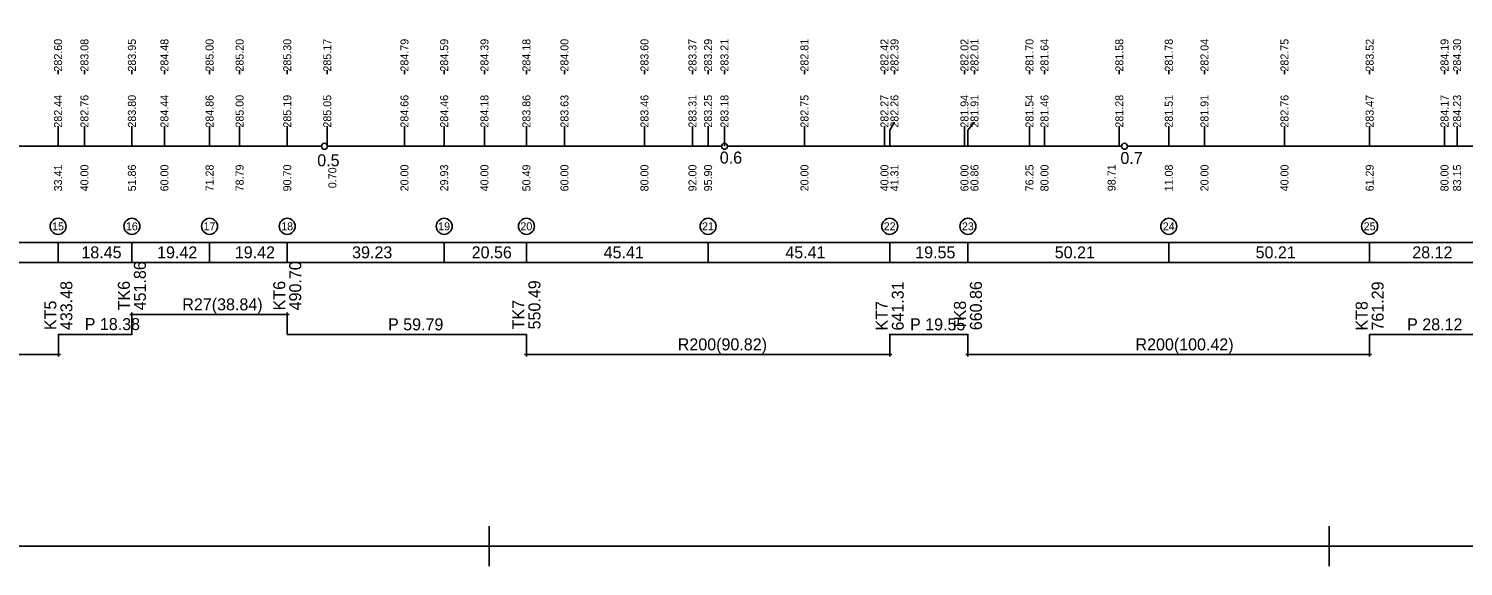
# Model space of a CAD drawing. Extents: x -24 to 1036, y -50 to 554.
# Drawn here: x 496.1 to 854.7, y -50 to 84.4 of the extents above; entities that cross this region are included whole.
import ezdxf

# ---------------------------------------------------------------- set-up
doc = ezdxf.new("R2010")
doc.units = 0
for name, color, linetype in [('SESTAVY_REZU_PO', 7, 'Continuous'), ('SMEROVE_POMERY', 7, 'Continuous'), ('SMEROVE_POMERY_KOD', 7, 'Continuous'), ('SVK', 7, 'Continuous'), ('SVK_STAT', 7, 'Continuous'), ('TABULKY', 7, 'Continuous')]:
    doc.layers.add(name, color=color, linetype=linetype)

msp = doc.modelspace()

# ---------------------------------------------------------------- linework, layer by layer
for p, q in [((611.15, -39.96), (611.15, -49.96)), ((611.15, -39.96), (611.15, -49.96)), ((611.15, -39.96), (611.15, -49.96)), ((611.15, -39.96), (611.15, -49.96)), ((611.15, -39.96), (611.15, -49.96)), ((611.15, -39.96), (611.15, -49.96)), ((611.15, -39.96), (611.15, -49.96)), ((611.15, -39.96), (611.15, -49.96)), ((611.15, -39.96), (611.15, -49.96)), ((611.15, -39.96), (611.15, -49.96)), ((611.15, -39.96), (611.15, -49.96)), ((611.15, -39.96), (611.15, -49.96)), ((611.15, -39.96), (611.15, -49.96)), ((611.15, -39.96), (611.15, -49.96)), ((611.15, -39.96), (611.15, -49.96)), ((611.15, -39.96), (611.15, -49.96)), ((821.15, -39.96), (821.15, -49.96)), ((821.15, -39.96), (821.15, -49.96)), ((821.15, -39.96), (821.15, -49.96)), ((821.15, -39.96), (821.15, -49.96)), ((821.15, -39.96), (821.15, -49.96)), ((821.15, -39.96), (821.15, -49.96)), ((821.15, -39.96), (821.15, -49.96)), ((821.15, -39.96), (821.15, -49.96)), ((616.15, -44.96), (606.15, -44.96)), ((616.15, -44.96), (606.15, -44.96)), ((616.15, -44.96), (606.15, -44.96)), ((616.15, -44.96), (606.15, -44.96)), ((616.15, -44.96), (606.15, -44.96)), ((616.15, -44.96), (606.15, -44.96)), ((616.15, -44.96), (606.15, -44.96)), ((616.15, -44.96), (606.15, -44.96)), ((616.15, -44.96), (606.15, -44.96)), ((616.15, -44.96), (606.15, -44.96)), ((616.15, -44.96), (606.15, -44.96)), ((616.15, -44.96), (606.15, -44.96)), ((616.15, -44.96), (606.15, -44.96)), ((616.15, -44.96), (606.15, -44.96)), ((616.15, -44.96), (606.15, -44.96)), ((616.15, -44.96), (606.15, -44.96)), ((826.15, -44.96), (816.15, -44.96)), ((826.15, -44.96), (816.15, -44.96)), ((826.15, -44.96), (816.15, -44.96)), ((826.15, -44.96), (816.15, -44.96)), ((826.15, -44.96), (816.15, -44.96)), ((826.15, -44.96), (816.15, -44.96)), ((826.15, -44.96), (816.15, -44.96)), ((826.15, -44.96), (816.15, -44.96))]:
    msp.add_line(p, q)
msp.add_lwpolyline([(1031.15, 549.04), (-19.35, 549.04), (-19.35, -44.96), (1031.15, -44.96)], close=True)
msp.add_lwpolyline([(1031.15, 549.04), (-19.35, 549.04), (-19.35, -44.96), (1031.15, -44.96)], close=True)
at = {"layer": 'SESTAVY_REZU_PO'}
for points in [[(470.75, 55), (569.25, 55)], [(570.75, 55), (669.25, 55)], [(670.75, 55), (769.25, 55)], [(770.75, 55), (859.4, 55)], [(503.41, 26), (503.41, 31)], [(521.86, 26), (521.86, 31)], [(541.28, 26), (541.28, 31)], [(560.7, 26), (560.7, 31)], [(599.93, 26), (599.93, 31)], [(620.49, 26), (620.49, 31)], [(665.9, 26), (665.9, 31)], [(711.31, 26), (711.31, 31)], [(730.86, 26), (730.86, 31)], [(781.08, 26), (781.08, 31)], [(831.29, 26), (831.29, 31)]]:
    msp.add_lwpolyline(points, dxfattribs=at)
for centre in [(570, 55), (670, 55), (770, 55)]:
    msp.add_circle(centre, 0.75, dxfattribs=at)
at = {"layer": 'SMEROVE_POMERY'}
msp.add_lwpolyline([(445.06, 3), (503.48, 3), (503.48, 8), (521.86, 8), (521.86, 13), (560.7, 13), (560.7, 8), (620.49, 8), (620.49, 3), (711.31, 3), (711.31, 8), (730.86, 8), (730.86, 3), (831.29, 3), (831.29, 8), (859.4, 8)], dxfattribs=at)
at = {"layer": 'SMEROVE_POMERY_KOD'}
for points in [[(521.36, 13), (522.36, 13)], [(521.86, 12.5), (521.86, 13.5)], [(560.2, 13), (561.2, 13)], [(560.7, 12.5), (560.7, 13.5)], [(502.98, 3), (503.98, 3)], [(503.48, 2.5), (503.48, 3.5)], [(619.99, 3), (620.99, 3)], [(620.49, 2.5), (620.49, 3.5)], [(710.81, 3), (711.81, 3)], [(711.31, 2.5), (711.31, 3.5)], [(730.36, 3), (731.36, 3)], [(730.86, 2.5), (730.86, 3.5)], [(830.79, 3), (831.79, 3)], [(831.29, 2.5), (831.29, 3.5)]]:
    msp.add_lwpolyline(points, dxfattribs=at)
at = {"layer": 'SVK'}
for points in [[(510, 73), (510, 74)], [(530, 73), (530, 74)], [(590, 73), (590, 74)], [(610, 73), (610, 74)], [(630, 73), (630, 74)], [(650, 73), (650, 74)], [(670, 73), (670, 74)], [(690, 73), (690, 74)], [(710, 73), (710, 74)], [(730, 73), (730, 74)], [(750, 73), (750, 74)], [(790, 73), (790, 74)], [(810, 73), (810, 74)], [(850, 73), (850, 74)], [(853.15, 73), (853.15, 74)], [(510, 55), (510, 60)], [(530, 55), (530, 60)], [(590, 55), (590, 60)], [(610, 55), (610, 60)], [(630, 55), (630, 60)], [(650, 55), (650, 60)], [(670, 55), (670, 60)], [(690, 55), (690, 60)], [(710, 55), (710, 60)], [(730, 55), (730, 60)], [(750, 55), (750, 60)], [(790, 55), (790, 60)], [(810, 55), (810, 60)], [(850, 55), (850, 60)], [(853.15, 55), (853.15, 60)]]:
    msp.add_lwpolyline(points, dxfattribs=at)
at = {"layer": 'SVK_STAT'}
for points in [[(503.41, 73), (503.41, 74)], [(521.86, 73), (521.86, 74)], [(541.28, 73), (541.28, 74)], [(548.79, 73), (548.79, 74)], [(560.7, 73), (560.7, 74)], [(570.7, 73), (570.7, 74)], [(599.93, 73), (599.93, 74)], [(620.49, 73), (620.49, 74)], [(662, 73), (662, 74)], [(665.9, 73), (665.9, 74)], [(712.5, 73), (712.5, 74)], [(732.5, 73), (732.5, 74)], [(746.25, 73), (746.25, 74)], [(768.71, 73), (768.71, 74)], [(781.08, 73), (781.08, 74)], [(831.29, 73), (831.29, 74)], [(711.31, 55), (711.31, 59), (712.5, 61)], [(730.86, 55), (730.86, 59), (732.5, 61)], [(503.41, 55), (503.41, 60)], [(521.86, 55), (521.86, 60)], [(541.28, 55), (541.28, 60)], [(548.79, 55), (548.79, 60)], [(560.7, 55), (560.7, 60)], [(570.7, 55), (570.7, 60)], [(599.93, 55), (599.93, 60)], [(620.49, 55), (620.49, 60)], [(662, 55), (662, 60)], [(665.9, 55), (665.9, 60)], [(746.25, 55), (746.25, 60)], [(768.71, 55), (768.71, 60)], [(781.08, 55), (781.08, 60)], [(831.29, 55), (831.29, 60)]]:
    msp.add_lwpolyline(points, dxfattribs=at)
for centre in [(503.41, 35), (521.86, 35), (541.28, 35), (560.7, 35), (599.93, 35), (620.49, 35), (665.9, 35), (711.31, 35), (730.86, 35), (781.08, 35), (831.29, 35)]:
    msp.add_circle(centre, 2, dxfattribs=at)
at = {"layer": 'TABULKY'}
msp.add_lwpolyline([(70, 26), (859.4, 26), (859.4, 31), (70, 31), (70, 26)], dxfattribs=at)

# ---------------------------------------------------------------- texts
at = {"layer": 'SESTAVY_REZU_PO'}
for s, p in [('0.5', (568.2, 50)), ('0.6', (668.83, 50.68)), ('0.7', (768.98, 50.58)), ('18.45', (509.24, 27)), ('19.42', (528.17, 27)), ('19.42', (547.59, 27)), ('39.23', (576.92, 27)), ('20.56', (606.81, 27)), ('45.41', (639.8, 27)), ('45.41', (685.21, 27)), ('19.55', (717.69, 27)), ('50.21', (752.57, 27)), ('50.21', (802.78, 27)), ('28.12', (841.95, 27))]:
    msp.add_text(s, height=3, dxfattribs=at).set_placement(p)
at = {"layer": 'SMEROVE_POMERY'}
for s, p in [('R27(38.84)', (534.47, 14)), ('P 18.38', (510.07, 9.07)), ('P 59.79', (585.9, 9)), ('P 19.55', (716.39, 9)), ('P 28.12', (840.65, 9)), ('R200(90.82)', (658.33, 4)), ('R200(100.42)', (772.75, 4))]:
    msp.add_text(s, height=3, dxfattribs=at).set_placement(p)
at = {"layer": 'SMEROVE_POMERY_KOD'}
for s, p in [('451.86', (525.36, 14)), ('490.70', (564.2, 14)), ('433.48', (506.98, 9.07)), ('TK6', (521.36, 14)), ('KT6', (560.2, 14)), ('550.49', (623.99, 9.24)), ('641.31', (714.81, 8.96)), ('660.86', (734.36, 9.03)), ('761.29', (834.79, 8.95)), ('KT5', (502.98, 9.07)), ('TK7', (619.99, 9.24)), ('KT7', (710.81, 8.96)), ('TK8', (730.36, 9.03)), ('KT8', (830.79, 8.95))]:
    msp.add_text(s, height=3, rotation=90, dxfattribs=at).set_placement(p)
at = {"layer": 'SVK'}
for s, p in [(' 283.08', (511, 72.93)), (' 284.48', (531, 72.93)), (' 284.79', (591, 72.93)), (' 284.39', (611, 72.93)), (' 284.00', (631, 72.93)), (' 283.60', (651, 72.93)), (' 283.21', (671, 72.93)), (' 282.81', (691, 72.93)), (' 282.42', (711, 72.93)), (' 282.02', (731, 72.93)), (' 281.64', (751, 72.93)), (' 282.04', (791, 72.93)), (' 282.75', (811, 72.93)), (' 284.19', (851, 72.93)), (' 284.30', (854.15, 72.93)), (' 282.76', (511, 58.93)), (' 284.44', (531, 58.93)), (' 284.66', (591, 58.93)), (' 284.18', (611, 58.93)), (' 283.63', (631, 58.93)), (' 283.46', (651, 58.93)), (' 283.18', (671, 58.93)), (' 282.75', (691, 58.93)), (' 282.27', (711, 58.93)), (' 281.94', (731, 58.93)), (' 281.46', (751, 58.93)), (' 281.91', (791, 58.93)), (' 282.76', (811, 58.93)), (' 284.17', (851, 58.93)), (' 284.23', (854.15, 58.93)), (' 40.00', (511, 43)), (' 60.00', (531, 43)), (' 20.00', (591, 43)), (' 40.00', (611, 43)), (' 60.00', (631, 43)), (' 80.00', (651, 43)), (' 20.00', (691, 43)), (' 40.00', (711, 43)), (' 60.00', (731, 43)), (' 80.00', (751, 43)), (' 20.00', (791, 43)), (' 40.00', (811, 43)), (' 80.00', (851, 43)), (' 83.15', (854.15, 43))]:
    msp.add_text(s, height=2, rotation=90, dxfattribs=at).set_placement(p)
at = {"layer": 'SVK_STAT'}
for s, p in [(' 282.60', (504.41, 72.93)), (' 283.95', (522.86, 72.93)), (' 285.00', (542.28, 72.93)), (' 285.20', (549.79, 72.93)), (' 285.30', (561.7, 72.93)), (' 285.17', (571.7, 72.93)), (' 284.59', (600.93, 72.93)), (' 284.18', (621.49, 72.93)), (' 283.37', (663, 72.93)), (' 283.29', (666.9, 72.93)), (' 282.39', (713.5, 72.93)), (' 282.01', (733.5, 72.93)), (' 281.70', (747.25, 72.93)), (' 281.58', (769.71, 72.93)), (' 281.78', (782.08, 72.93)), (' 283.52', (832.29, 72.93)), (' 282.44', (504.41, 58.93)), (' 283.80', (522.86, 58.93)), (' 284.86', (542.28, 58.93)), (' 285.00', (549.79, 58.93)), (' 285.19', (561.7, 58.93)), (' 285.05', (571.7, 58.93)), (' 284.46', (600.93, 58.93)), (' 283.86', (621.49, 58.93)), (' 283.31', (663, 58.93)), (' 283.25', (666.9, 58.93)), (' 282.26', (713.5, 58.93)), (' 281.91', (733.5, 58.93)), (' 281.54', (747.25, 58.93)), (' 281.28', (769.71, 58.93)), (' 281.51', (782.08, 58.93)), (' 283.47', (832.29, 58.93)), (' 33.41', (504.41, 43)), (' 51.86', (522.86, 43)), (' 71.28', (542.28, 43)), (' 78.79', (549.79, 43)), (' 90.70', (561.7, 43)), (' 29.93', (600.93, 43)), (' 50.49', (621.49, 43)), (' 92.00', (663, 43)), (' 95.90', (666.9, 43)), (' 41.31', (713.5, 43)), (' 60.86', (733.5, 43)), (' 76.25', (747.25, 43)), (' 98.71', (767.78, 43.04)), (' 11.08', (782.08, 43)), (' 61.29', (832.29, 43)), ('  0.70', (572.97, 43.04))]:
    msp.add_text(s, height=2, rotation=90, dxfattribs=at).set_placement(p)
for s, p in [('15', (501.91, 34)), ('16', (520.36, 34)), ('17', (539.77, 34)), ('18', (559.19, 34)), ('19', (598.42, 34)), ('20', (618.99, 34)), ('21', (664.39, 34)), ('22', (709.8, 34)), ('23', (729.36, 34)), ('24', (779.57, 34)), ('25', (829.78, 34))]:
    msp.add_text(s, height=2, dxfattribs=at).set_placement(p)

doc.saveas('drawing.dxf')
